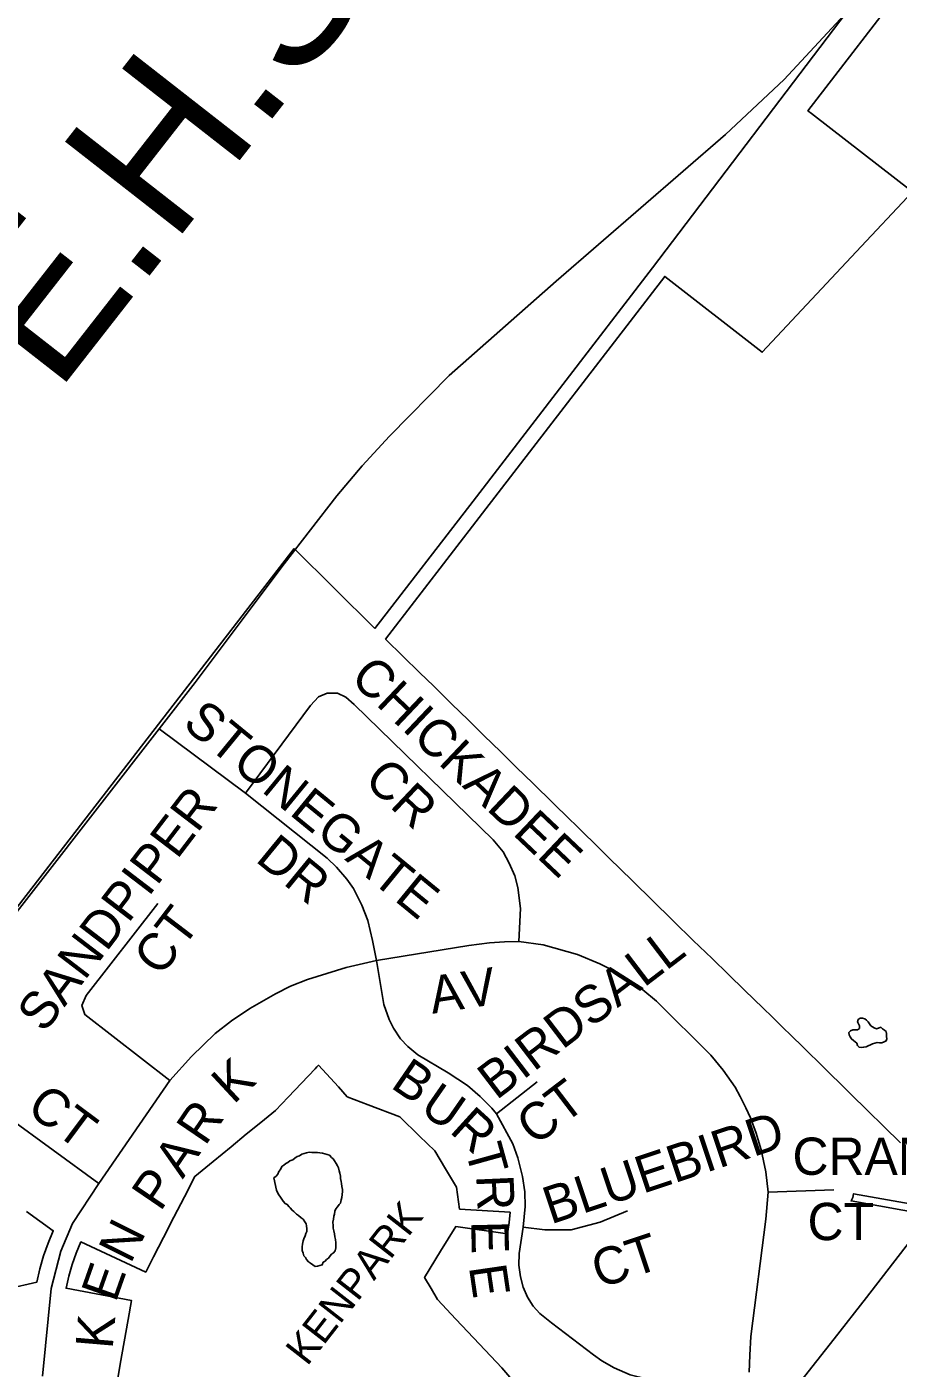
# Model space of a CAD drawing. Extents: x 586326 to 623965, y 4819854 to 4857850.
# Drawn here: x 595698 to 596282, y 4844078 to 4844977 of the extents above; entities that cross this region are included whole.
import ezdxf

# ---------------------------------------------------------------- set-up
doc = ezdxf.new("R2010")
doc.units = 0
for name, color, linetype in [('Lots_Concessions', 7, 'Continuous'), ('Major Rds and Hwys', 7, 'Continuous'), ('Minor Rd Lbls', 7, 'Continuous'), ('Minor Rds', 7, 'Continuous'), ('Municipal Bdry', 7, 'Continuous'), ('Park Lbls', 7, 'Continuous'), ('Park Outlines', 7, 'Continuous')]:
    doc.layers.add(name, color=color, linetype=linetype)

msp = doc.modelspace()

# ---------------------------------------------------------------- linework, layer by layer
at = {"layer": 'Lots_Concessions'}
for p, q in [((596260.94, 4844125.09), (596289.85, 4844162.32)), ((596239.35, 4844097.28), (596260.94, 4844125.09)), ((596200.53, 4844048.26), (596239.35, 4844097.28))]:
    msp.add_line(p, q, dxfattribs=at)
at = {"layer": 'Major Rds and Hwys'}
for points in [[(595786.69, 4844506.42), (595810.77, 4844537.53), (595870.47, 4844617.09), (595905.8, 4844662.67), (595922.8, 4844682.8), (595941.2, 4844702.74), (595981.26, 4844743.5), (596052.94, 4844806.73), (596166.35, 4844905.12), (596205.68, 4844941.89), (596249.04, 4844988.73), (596280.88, 4845029.16), (596345.89, 4845114.54)], [(595457.19, 4844082.75), (595786.69, 4844506.42)]]:
    msp.add_lwpolyline(points, dxfattribs=at)
at = {"layer": 'Minor Rds'}
for points in [[(595844.58, 4844463.4), (595888.24, 4844522.19), (595893.54, 4844528.04), (595899.3, 4844530.34), (595906.28, 4844530.34), (595911.93, 4844527.64), (595917.34, 4844522.77), (596010.61, 4844432.06), (596017.33, 4844424.01), (596021.48, 4844416.48), (596025.23, 4844407.79), (596027.1, 4844400.07), (596029.01, 4844386.07), (596027.94, 4844363.86)], [(595844.58, 4844463.4), (595786.69, 4844506.42)], [(595932.48, 4844351.05), (595929.74, 4844364.46), (595926.61, 4844377.82), (595922.57, 4844388.31), (595917, 4844399.32), (595912.52, 4844405.67), (595905.64, 4844413.63), (595899.39, 4844419.82), (595844.58, 4844463.4)], [(595793.79, 4844270.67), (595736.87, 4844314.78), (595734.93, 4844320.99), (595737.65, 4844327.59), (595785.79, 4844389.32)], [(595932.48, 4844351.05), (595994.35, 4844361.22), (596008.3, 4844362.93), (596018.29, 4844363.71), (596027.94, 4844363.86)], [(596027.94, 4844363.86), (596044.24, 4844361.53), (596067.2, 4844355.07), (596082.16, 4844348.85), (596094.3, 4844342.9), (596110.99, 4844331.52), (596120.19, 4844323.76), (596156.58, 4844287.6), (596164.98, 4844277.53), (596172.83, 4844266.21), (596176.38, 4844259.87), (596180.05, 4844252.23), (596183.17, 4844245.58), (596187.05, 4844235.18), (596190.27, 4844224.19), (596193.5, 4844209.46), (596194.95, 4844195.82)], [(595793.79, 4844270.67), (595808.3, 4844286.82), (595824.23, 4844302.05), (595835.28, 4844310.71), (595847.59, 4844318.87), (595864.68, 4844328.73), (595874.77, 4844333.86), (595886.05, 4844338.38), (595912.1, 4844346.4), (595932.48, 4844351.05)], [(596012.92, 4844248.19), (596009.71, 4844252), (596001.96, 4844259.78), (595993.37, 4844267.21), (595980.53, 4844275.66), (595960.03, 4844287.93), (595953.47, 4844293.35), (595948.5, 4844298.62), (595943.78, 4844305.81), (595940.82, 4844311.43), (595937.39, 4844321.6), (595932.48, 4844351.05)], [(595746.21, 4844201.46), (595793.79, 4844270.67)], [(596012.92, 4844248.19), (596040.26, 4844269.73)], [(595746.21, 4844201.46), (595685.09, 4844246.28), (595676.94, 4844246.86), (595669.37, 4844242.2), (595605.64, 4844157.06), (595603.23, 4844141.78)], [(596030.85, 4844172.35), (596032.1, 4844186.13), (596031.79, 4844195.87), (596030.36, 4844206.21), (596027.11, 4844218.82), (596023.87, 4844228.12), (596012.92, 4844248.19)], [(595708.38, 4844072.32), (595714.19, 4844131.02), (595720.77, 4844156.19), (595728.66, 4844174.8), (595746.21, 4844201.46)], [(596194.95, 4844195.82), (596193.58, 4844177.52), (596183.51, 4844098.92), (596182.78, 4844086.37), (596182.3, 4844075.04)], [(596194.95, 4844195.82), (596239.05, 4844197.38)], [(596030.85, 4844172.35), (596045.32, 4844170.49), (596063.01, 4844170.39), (596082.44, 4844175.6), (596100.81, 4844183.24)], [(596113.51, 4844070.48), (596102.45, 4844073.3), (596091.85, 4844077.98), (596083.61, 4844082.54), (596077.86, 4844086.6), (596049.69, 4844108.04), (596041.87, 4844114.43), (596037.4, 4844119.22), (596033.67, 4844125.31), (596030.83, 4844131.99), (596029.01, 4844138.88), (596027.96, 4844146.75), (596028.14, 4844154.53), (596030.85, 4844172.35)]]:
    msp.add_lwpolyline(points, dxfattribs=at)
at = {"layer": 'Municipal Bdry'}
for p, q in [((596117.5, 4844815.65), (596252.22, 4844993.21)), ((595997.16, 4844659.22), (596117.5, 4844815.65)), ((595931.34, 4844573.68), (595997.16, 4844659.22)), ((595656.35, 4844341.43), (595877.31, 4844627.36)), ((595877.31, 4844627.36), (595931.34, 4844573.68))]:
    msp.add_line(p, q, dxfattribs=at)
at = {"layer": 'Park Outlines'}
for points in [[(596290.25, 4845010.22), (596221.67, 4844921.08), (596224.17, 4844919.14), (596291.79, 4844866.57), (596254.03, 4844826.5), (596191.12, 4844759.07), (596125.75, 4844809.89), (596003.56, 4844651.07), (595938.53, 4844566.54), (595950.36, 4844554.98), (595961.23, 4844544.36), (595970.8, 4844535.02), (595972.1, 4844533.74), (595982.95, 4844523.11), (595993.81, 4844512.48), (596004.66, 4844501.84), (596015.52, 4844491.21), (596026.37, 4844480.57), (596037.22, 4844469.94), (596051.16, 4844456.29), (596061.3, 4844446.35), (596066.44, 4844441.31), (596083.44, 4844424.66), (596088.52, 4844419.69), (596103.81, 4844404.71), (596118.09, 4844390.72), (596130.25, 4844378.81), (596131.67, 4844377.43), (596144.86, 4844364.62), (596157.46, 4844352.36), (596168.36, 4844341.77), (596179.26, 4844331.18), (596191.75, 4844319.04), (596197.69, 4844313.27), (596204.93, 4844306.24), (596210.44, 4844300.88), (596218.46, 4844293), (596232.6, 4844279.09), (596247.71, 4844264.23), (596250.53, 4844261.46), (596283.84, 4844228.7)], [(596028.25, 4844064.06), (596016.41, 4844077.84), (596001.54, 4844093.71), (595985.71, 4844110.59), (595973.4, 4844123.72), (595969.02, 4844131.14), (595964.63, 4844138.58), (595975.43, 4844156.11), (595985.6, 4844172.63), (596020.24, 4844167.72), (596021.31, 4844175.28), (596022.02, 4844182.26), (595988.1, 4844184.38), (595986.08, 4844198.99), (595978.66, 4844211.44), (595971.52, 4844223.43), (595961.31, 4844233.33), (595948.08, 4844246.16), (595926.83, 4844254.36), (595912.84, 4844259.76), (595906.87, 4844266.3), (595893.59, 4844280.82), (595892.49, 4844279.67), (595891.39, 4844278.51), (595882.22, 4844268.89), (595873.29, 4844259.52), (595864.62, 4844250.42), (595854.96, 4844242.54), (595845.12, 4844234.51), (595834.94, 4844226.21), (595822.82, 4844216.33), (595810.54, 4844206.31), (595803.58, 4844192.67), (595796.61, 4844179.03), (595789.64, 4844165.39), (595782.94, 4844152.28), (595777.73, 4844142.07), (595734.24, 4844162.35), (595731.02, 4844154.84), (595728.28, 4844147.14), (595726.03, 4844139.28), (595724.27, 4844131.3), (595768.09, 4844123.1), (595765.86, 4844110.35), (595763.24, 4844095.32), (595760.61, 4844080.3), (595757.98, 4844065.28)], [(596301.77, 4844185.82), (596252.38, 4844194.6), (596251.73, 4844192.14), (596250.67, 4844189.82), (596303.87, 4844180.37)], [(595685.18, 4844130.83), (595704.69, 4844135.39), (595706.66, 4844144.25), (595709.15, 4844152.97), (595712.17, 4844161.53), (595715.7, 4844169.89), (595697.71, 4844182.78)]]:
    msp.add_lwpolyline(points, dxfattribs=at)
for points in [[(596256.26, 4844305.54), (596254.97, 4844304.52), (596253.33, 4844304.69), (596251.8, 4844304.52), (596250.27, 4844303.95), (596249.13, 4844302.74), (596249.43, 4844301.22), (596249.98, 4844299.8), (596250.91, 4844298.55), (596252.17, 4844297.5), (596253.33, 4844296.52), (596254.52, 4844295.58), (596255.03, 4844294.14), (596256.01, 4844292.95), (596257.54, 4844292.71), (596259.13, 4844293.04), (596260.72, 4844293.24), (596262.21, 4844293.95), (596263.57, 4844294.62), (596265.01, 4844295.13), (596266.63, 4844295.7), (596268.16, 4844296.1), (596269.78, 4844295.92), (596271.28, 4844295.96), (596272.77, 4844296.45), (596274.2, 4844297.15), (596274.59, 4844298.64), (596274.37, 4844300.19), (596274.42, 4844301.8), (596274.18, 4844303.42), (596272.96, 4844304.35), (596271.66, 4844305.25), (596270.54, 4844306.34), (596269.07, 4844305.69), (596267.61, 4844305.2), (596266.22, 4844305.85), (596263.85, 4844307.36), (596262.9, 4844308.56), (596262.07, 4844309.85), (596261.01, 4844311.03), (596259.82, 4844311.96), (596258.39, 4844312.48), (596256.78, 4844312.41), (596255.43, 4844311.51), (596255.04, 4844309.96), (596255.55, 4844308.53), (596256.26, 4844307.17)], [(596257.54, 4844292.71), (596256.01, 4844292.95), (596255.03, 4844294.14), (596254.52, 4844295.58), (596253.33, 4844296.52), (596252.17, 4844297.5), (596250.91, 4844298.55), (596249.98, 4844299.8), (596249.43, 4844301.22), (596249.13, 4844302.74), (596250.27, 4844303.95), (596251.8, 4844304.52), (596253.33, 4844304.69), (596254.97, 4844304.52), (596256.26, 4844305.54), (596256.26, 4844307.17), (596255.55, 4844308.53), (596255.04, 4844309.96), (596255.43, 4844311.51), (596256.78, 4844312.41), (596258.39, 4844312.48), (596259.82, 4844311.96), (596261.01, 4844311.03), (596262.07, 4844309.85), (596262.9, 4844308.56), (596263.85, 4844307.36), (596266.22, 4844305.85), (596267.61, 4844305.2), (596269.07, 4844305.69), (596270.54, 4844306.34), (596271.66, 4844305.25), (596272.96, 4844304.35), (596274.18, 4844303.42), (596274.42, 4844301.8), (596274.37, 4844300.19), (596274.59, 4844298.64), (596274.2, 4844297.15), (596272.77, 4844296.45), (596271.28, 4844295.96), (596269.78, 4844295.92), (596268.16, 4844296.1), (596266.63, 4844295.7), (596265.01, 4844295.13), (596263.57, 4844294.62), (596262.21, 4844293.95), (596260.72, 4844293.24), (596259.13, 4844293.04)], [(595892.82, 4844146.03), (595891.41, 4844145.86), (595889.72, 4844146.95), (595888.07, 4844148.08), (595886.85, 4844148.95), (595885.58, 4844150.58), (595884.74, 4844151.94), (595883.72, 4844153.06), (595883.23, 4844154.87), (595882.62, 4844156.54), (595882.63, 4844158.99), (595882.88, 4844160.93), (595883.25, 4844163.03), (595883.78, 4844164.52), (595884.58, 4844166.35), (595885.15, 4844167.89), (595885.64, 4844169.33), (595885.7, 4844171.03), (595885.44, 4844173.13), (595885.19, 4844174.44), (595884.43, 4844175.91), (595883.2, 4844177.58), (595881.94, 4844178.4), (595880.13, 4844180.14), (595878.83, 4844180.92), (595877.01, 4844182.65), (595875.83, 4844183.58), (595874.52, 4844185.15), (595873.85, 4844185.92), (595872.54, 4844187.49), (595871.13, 4844188.12), (595869.79, 4844189.65), (595868.91, 4844190.96), (595868.15, 4844192.43), (595866.85, 4844194.01), (595866.05, 4844195.42), (595865.37, 4844196.99), (595863.63, 4844205.32), (595865.06, 4844206.34), (595866.26, 4844207.87), (595866.94, 4844209.56), (595868.02, 4844210.94), (595869.01, 4844213.02), (595870.33, 4844213.89), (595871.72, 4844214.86), (595872.88, 4844215.54), (595874.39, 4844216.66), (595876.26, 4844217.42), (595877.77, 4844218.55), (595879.28, 4844219.67), (595880.88, 4844220.08), (595882.31, 4844221.11), (595883.94, 4844221.57), (595885.54, 4844221.99), (595887.17, 4844222.46), (595889.01, 4844222.37), (595890.92, 4844222.39), (595892.8, 4844222.35), (595894.44, 4844222.02), (595896.28, 4844221.93), (595897.81, 4844221.45), (595899.33, 4844220.97), (595900.86, 4844220.49), (595902.28, 4844219.06), (595903.35, 4844217.99), (595904.19, 4844216.62), (595905.42, 4844214.95), (595906.18, 4844213.48), (595906.93, 4844212.02), (595907.35, 4844210.11), (595907.91, 4844208.4), (595908.21, 4844206.34), (595908.38, 4844204.94), (595908.68, 4844202.88), (595908.93, 4844201.58), (595909.26, 4844199.57), (595909.6, 4844197.56), (595909.69, 4844196.06), (595909.44, 4844194.12), (595909.12, 4844192.07), (595908.63, 4844190.63), (595908.18, 4844188.44), (595907.41, 4844187.45), (595906.26, 4844185.98), (595905.1, 4844184.5), (595904.5, 4844182.91), (595904.17, 4844180.87), (595903.76, 4844179.52), (595903.5, 4844177.58), (595903.25, 4844175.63), (595903.43, 4844173.43), (595903.3, 4844171.63), (595903.83, 4844169.87), (595904.16, 4844167.86), (595904.5, 4844165.86), (595904.87, 4844163.9), (595905.17, 4844161.84), (595905.07, 4844160.1), (595905.09, 4844158.49), (595904.72, 4844156.4), (595903.65, 4844155.02), (595902.29, 4844154.1), (595901.41, 4844152.97), (595900.25, 4844151.49), (595898.93, 4844150.61), (595898.05, 4844149.48), (595896.77, 4844148.66), (595896.01, 4844146.87), (595894.49, 4844146.55)], [(595892.82, 4844146.03), (595894.49, 4844146.55), (595896.01, 4844146.87), (595896.77, 4844148.66), (595898.05, 4844149.48), (595898.93, 4844150.61), (595900.25, 4844151.49), (595901.41, 4844152.97), (595902.29, 4844154.1), (595903.65, 4844155.02), (595904.72, 4844156.4), (595905.09, 4844158.49), (595905.07, 4844160.1), (595905.17, 4844161.84), (595904.87, 4844163.9), (595904.5, 4844165.86), (595904.16, 4844167.86), (595903.83, 4844169.87), (595903.3, 4844171.63), (595903.43, 4844173.43), (595903.25, 4844175.63), (595903.5, 4844177.58), (595903.76, 4844179.52), (595904.17, 4844180.87), (595904.5, 4844182.91), (595905.1, 4844184.5), (595906.26, 4844185.98), (595907.41, 4844187.45), (595908.18, 4844188.44), (595908.63, 4844190.63), (595909.12, 4844192.07), (595909.44, 4844194.12), (595909.69, 4844196.06), (595909.6, 4844197.56), (595909.26, 4844199.57), (595908.93, 4844201.58), (595908.68, 4844202.88), (595908.38, 4844204.94), (595908.21, 4844206.34), (595907.91, 4844208.4), (595907.35, 4844210.11), (595906.93, 4844212.02), (595906.18, 4844213.48), (595905.42, 4844214.95), (595904.19, 4844216.62), (595903.35, 4844217.99), (595902.28, 4844219.06), (595900.86, 4844220.49), (595899.33, 4844220.97), (595897.81, 4844221.45), (595896.28, 4844221.93), (595894.44, 4844222.02), (595892.8, 4844222.35), (595890.92, 4844222.39), (595889.01, 4844222.37), (595887.17, 4844222.46), (595885.54, 4844221.99), (595883.94, 4844221.57), (595882.31, 4844221.11), (595880.88, 4844220.08), (595879.28, 4844219.67), (595877.77, 4844218.55), (595876.26, 4844217.42), (595874.39, 4844216.66), (595872.88, 4844215.54), (595871.72, 4844214.86), (595870.33, 4844213.89), (595869.01, 4844213.02), (595868.02, 4844210.94), (595866.94, 4844209.56), (595866.26, 4844207.87), (595865.06, 4844206.34), (595863.63, 4844205.32), (595865.37, 4844196.99), (595866.05, 4844195.42), (595866.85, 4844194.01), (595868.15, 4844192.43), (595868.91, 4844190.96), (595869.79, 4844189.65), (595871.13, 4844188.12), (595872.54, 4844187.49), (595873.85, 4844185.92), (595874.52, 4844185.15), (595875.83, 4844183.58), (595877.01, 4844182.65), (595878.83, 4844180.92), (595880.13, 4844180.14), (595881.94, 4844178.4), (595883.2, 4844177.58), (595884.43, 4844175.91), (595885.19, 4844174.44), (595885.44, 4844173.13), (595885.7, 4844171.03), (595885.64, 4844169.33), (595885.15, 4844167.89), (595884.58, 4844166.35), (595883.78, 4844164.52), (595883.25, 4844163.03), (595882.88, 4844160.93), (595882.63, 4844158.99), (595882.62, 4844156.54), (595883.23, 4844154.87), (595883.72, 4844153.06), (595884.74, 4844151.94), (595885.58, 4844150.58), (595886.85, 4844148.95), (595888.07, 4844148.08), (595889.72, 4844146.95), (595891.41, 4844145.86)]]:
    msp.add_lwpolyline(points, close=True, dxfattribs=at)

# ---------------------------------------------------------------- texts
at = {"layer": 'Lots_Concessions'}
msp.add_text('CN 2 E.H.S.', height=100, rotation=52.00002, dxfattribs=at).set_placement((595507.4, 4844461.2))
at = {"layer": 'Minor Rd Lbls'}
for s, height, rotation, p in [('CHICKADEE', 25.002, 316.53163, (595913.85, 4844539.5)), (' STONEGATE', 25.002, 320.64827, (595794.3, 4844514.27)), ('CR', 25.002, 316.53163, (595923.15, 4844471)), ('SANDPIPER', 25.002, 52.62421, (595709.59, 4844301.75)), ('DR', 25.002, 320.64827, (595850.47, 4844418.1)), ('CT', 25.002, 52.62421, (595787.68, 4844339.47)), ('BIRDSALL', 25.002, 37.34937, (596012.78, 4844257.06)), ('AV', 25.002, 8.67319, (595969.89, 4844315.33)), ('K', 25, 42.87892, (595836.47, 4844254.1)), ('B', 25, 325.56423, (595941.09, 4844266.33)), ('U', 25, 325.22219, (595960.39, 4844249.94)), ('CT', 25.002, 37.34937, (596038.7, 4844226.22)), ('CT', 25.002, 323.3103, (595696.71, 4844249.88)), ('R', 25, 55.73891, (595817.47, 4844226.1)), ('R', 25, 317.72633, (595980.69, 4844236.29)), ('BLUEBIRD', 25.002, 18.43497, (596049.3, 4844173.99)), ('CRANBROOKE', 25.002, 0.00002, (596211.36, 4844207.33)), ('A', 25, 55.73891, (595802.47, 4844204.1)), ('T', 25, 285.53583, (595991.61, 4844224.58)), ('P', 25, 55.73891, (595787.47, 4844182.1)), ('R', 25, 272.48957, (595999.26, 4844206.93)), ('CT', 25.002, 0.00002, (596221.47, 4844163.54)), ('N', 25, 63.43497, (595767.47, 4844147.1)), ('E', 25, 271.31476, (595995.85, 4844176.3)), ('CT', 25.002, 18.43497, (596081.9, 4844130.97)), ('E', 25, 70.55998, (595757.47, 4844121.1)), ('E', 25, 278.29003, (595994.34, 4844145.7)), ('K', 25, 85.1355, (595755.47, 4844090.1))]:
    msp.add_text(s, height=height, rotation=rotation, dxfattribs=at).set_placement(p)
at = {"layer": 'Park Lbls'}
msp.add_text('KENPARK', height=19.992, rotation=52.00002, dxfattribs=at).set_placement((595885.89, 4844078.48))

doc.saveas('drawing.dxf')
